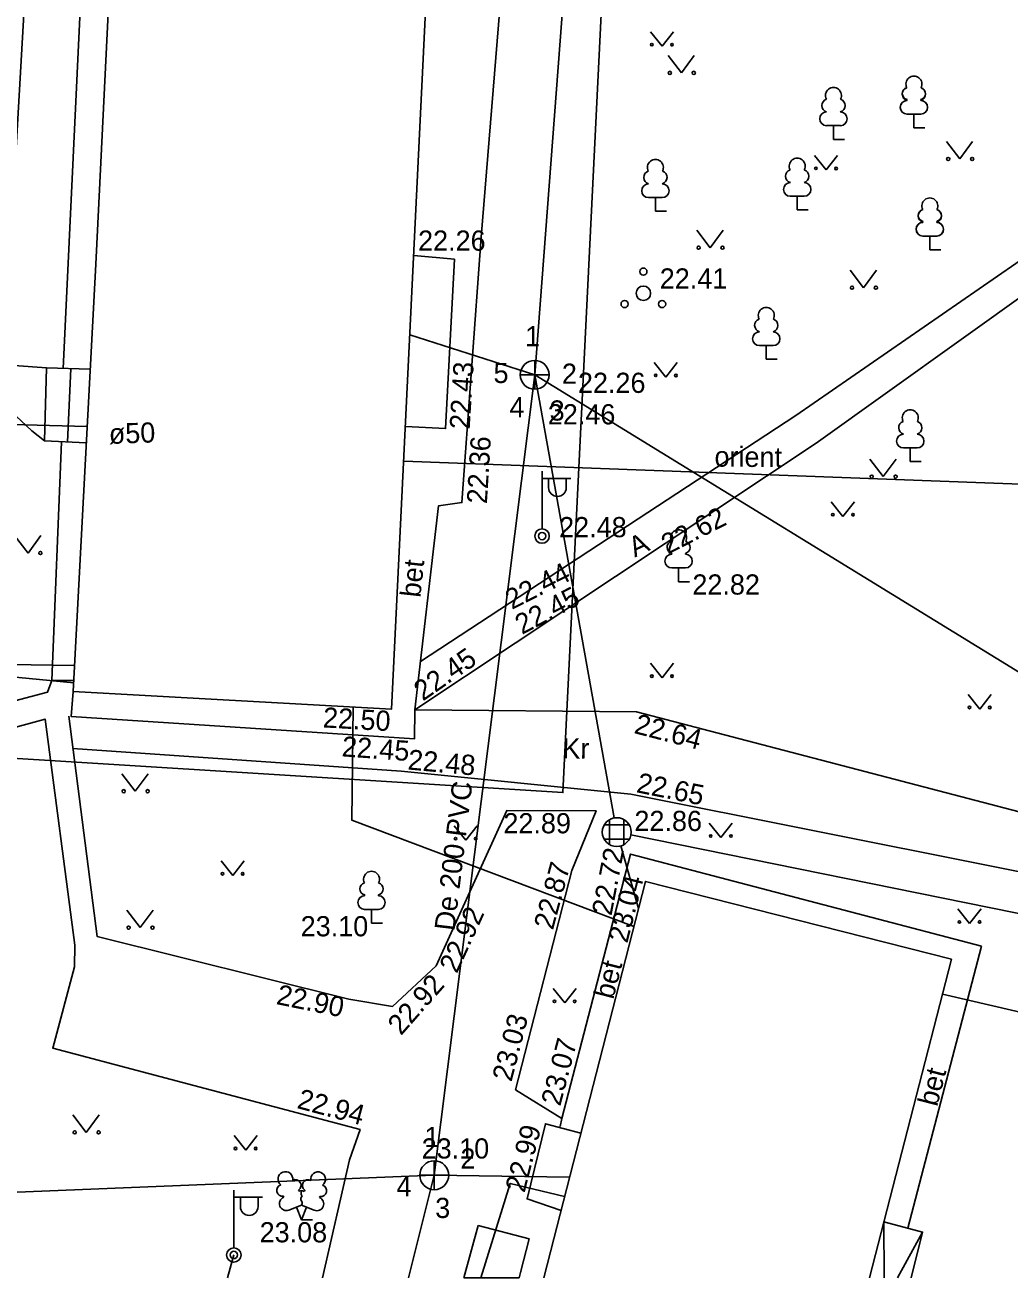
# Model space of a CAD drawing. Extents: x 714391 to 714584, y 6589993 to 6590151.
# Drawn here: x 714456.74 to 714490.89, y 6589992.71 to 6590036.16 of the extents above; entities that cross this region are included whole.
import ezdxf

# ---------------------------------------------------------------- set-up
doc = ezdxf.new("R2010")
doc.units = 0
for name, color, linetype in [('DKAEV', 7, 'Continuous'), ('HALJASTUS', 7, 'Continuous'), ('HOONE', 7, 'Continuous'), ('HOONEDET', 7, 'Continuous'), ('KKAEV', 7, 'Continuous'), ('KORGUS', 7, 'Continuous'), ('KTRASS', 7, 'Continuous'), ('MPKAABEL', 7, 'Continuous'), ('POST', 7, 'Continuous'), ('PUU', 7, 'Continuous'), ('SITRASS', 7, 'Continuous'), ('SKTRASS', 7, 'Continuous'), ('TEE', 7, 'Continuous'), ('TORU NR', 7, 'Continuous'), ('TTRASS', 7, 'Continuous'), ('Слой 1', 7, 'Continuous')]:
    doc.layers.add(name, color=color, linetype=linetype)

msp = doc.modelspace()

# ---------------------------------------------------------------- linework, layer by layer
at = {"layer": 'DKAEV'}
for p, q in [((714476.824, 6590008.422), (714477.69, 6590008.422)), ((714477.007, 6590007.739), (714477.007, 6590008.605)), ((714477.507, 6590008.605), (714477.507, 6590007.739)), ((714477.69, 6590007.922), (714476.824, 6590007.922))]:
    msp.add_line(p, q, dxfattribs=at)
msp.add_circle((714477.257, 6590008.172), 0.5, dxfattribs=at)
at = {"layer": 'HALJASTUS'}
for p, q in [((714478.422, 6590035.928), (714478.827, 6590035.423)), ((714478.827, 6590035.423), (714479.222, 6590035.928)), ((714479.037, 6590035.107), (714479.5, 6590034.5)), ((714479.5, 6590034.5), (714479.946, 6590035.107)), ((714488.691, 6590032.123), (714489.154, 6590031.516)), ((714489.154, 6590031.516), (714489.6, 6590032.123)), ((714484.111, 6590031.638), (714484.516, 6590031.133)), ((714484.516, 6590031.133), (714484.911, 6590031.638)), ((714480.034, 6590029.044), (714480.497, 6590028.437)), ((714480.497, 6590028.437), (714480.943, 6590029.044)), ((714485.354, 6590027.657), (714485.817, 6590027.05)), ((714485.817, 6590027.05), (714486.263, 6590027.657)), ((714478.558, 6590024.459), (714478.963, 6590023.954)), ((714478.963, 6590023.954), (714479.358, 6590024.459)), ((714486.037, 6590021.107), (714486.5, 6590020.5)), ((714486.5, 6590020.5), (714486.946, 6590021.107)), ((714484.698, 6590019.627), (714485.103, 6590019.122)), ((714485.103, 6590019.122), (714485.498, 6590019.627)), ((714456.377, 6590018.457), (714456.84, 6590017.85)), ((714456.84, 6590017.85), (714457.286, 6590018.457)), ((714478.422, 6590014.028), (714478.827, 6590013.523)), ((714478.827, 6590013.523), (714479.222, 6590014.028)), ((714489.439, 6590012.945), (714489.844, 6590012.44)), ((714489.844, 6590012.44), (714490.239, 6590012.945)), ((714460.097, 6590010.197), (714460.56, 6590009.59)), ((714460.56, 6590009.59), (714461.006, 6590010.197)), ((714471.615, 6590008.395), (714472.02, 6590007.89)), ((714472.02, 6590007.89), (714472.415, 6590008.395)), ((714480.465, 6590008.486), (714480.87, 6590007.981)), ((714480.87, 6590007.981), (714481.265, 6590008.486)), ((714463.533, 6590007.176), (714463.938, 6590006.671)), ((714463.938, 6590006.671), (714464.333, 6590007.176)), ((714460.267, 6590005.467), (714460.73, 6590004.86)), ((714460.73, 6590004.86), (714461.176, 6590005.467)), ((714489.09, 6590005.506), (714489.495, 6590005.001)), ((714489.495, 6590005.001), (714489.89, 6590005.506)), ((714475.047, 6590002.751), (714475.452, 6590002.246)), ((714475.452, 6590002.246), (714475.847, 6590002.751)), ((714458.397, 6589998.367), (714458.86, 6589997.76)), ((714458.86, 6589997.76), (714459.306, 6589998.367)), ((714463.984, 6589997.649), (714464.389, 6589997.144)), ((714464.389, 6589997.144), (714464.784, 6589997.649))]:
    msp.add_line(p, q, dxfattribs=at)
for centre, radius in [((714478.474, 6590035.478), 0.0428), ((714479.174, 6590035.478), 0.0452), ((714479.099, 6590034.5), 0.055), ((714479.928, 6590034.5), 0.055), ((714488.753, 6590031.516), 0.055), ((714489.582, 6590031.516), 0.055), ((714484.163, 6590031.188), 0.0428), ((714484.863, 6590031.188), 0.0452), ((714480.096, 6590028.437), 0.055), ((714480.925, 6590028.437), 0.055), ((714478.18, 6590027.609), 0.125), ((714478.18, 6590026.859), 0.25), ((714485.416, 6590027.05), 0.055), ((714486.245, 6590027.05), 0.055), ((714477.53, 6590026.484), 0.125), ((714478.83, 6590026.484), 0.125), ((714478.61, 6590024.009), 0.0428), ((714479.31, 6590024.009), 0.0452), ((714486.099, 6590020.5), 0.055), ((714486.928, 6590020.5), 0.055), ((714484.75, 6590019.178), 0.0428), ((714485.45, 6590019.178), 0.0452), ((714457.268, 6590017.85), 0.055), ((714478.474, 6590013.579), 0.0428), ((714479.174, 6590013.579), 0.0452), ((714489.491, 6590012.495), 0.0428), ((714490.191, 6590012.495), 0.0452), ((714460.159, 6590009.59), 0.055), ((714460.988, 6590009.59), 0.055), ((714471.667, 6590007.946), 0.0428), ((714472.367, 6590007.946), 0.0452), ((714480.517, 6590008.036), 0.0428), ((714481.217, 6590008.036), 0.0452), ((714463.585, 6590006.727), 0.0428), ((714464.285, 6590006.727), 0.0452), ((714460.329, 6590004.86), 0.055), ((714461.158, 6590004.86), 0.055), ((714489.142, 6590005.056), 0.0428), ((714489.842, 6590005.056), 0.0452), ((714475.099, 6590002.302), 0.0428), ((714475.799, 6590002.302), 0.0452), ((714458.459, 6589997.76), 0.055), ((714459.288, 6589997.76), 0.055), ((714464.036, 6589997.199), 0.0428), ((714464.736, 6589997.199), 0.0452)]:
    msp.add_circle(centre, radius, dxfattribs=at)
at = {"layer": 'HOONE'}
for points in [[(714458.41, 6590013.05), (714459.19, 6590027.87), (714460.78, 6590060.09), (714461.543, 6590073.769), (714472.409, 6590073.228), (714469.451, 6590012.441), (714458.41, 6590013.05)], [(714458.89, 6590022.24), (714455.84, 6590022.32), (714456.07, 6590025.65), (714456.9, 6590040.18), (714456.96, 6590042.47)], [(714470.216, 6590028.163), (714471.627, 6590028.037), (714471.323, 6590022.165), (714469.928, 6590022.237)], [(714474.728, 6589992.711), (714478.254, 6590006.46), (714488.871, 6590003.761)], [(714488.871, 6590003.761), (714486.02, 6589992.711)], [(714475.327, 6589995.047), (714474.146, 6589995.449), (714474.786, 6589998.057), (714476.016, 6589997.731)], [(714472.545, 6589992.711), (714473.561, 6589995.989), (714475.451, 6589995.53)], [(714487.462, 6589992.711), (714487.862, 6589994.302), (714486.522, 6589994.654)]]:
    msp.add_lwpolyline(points, dxfattribs=at)
at = {"layer": 'HOONEDET'}
for p, q in [((714486.522, 6589994.654), (714486.526, 6589992.711)), ((714487.862, 6589994.302), (714486.989, 6589992.711))]:
    msp.add_line(p, q, dxfattribs=at)
for points in [[(714458.41, 6590013.05), (714458.331, 6590012.184), (714470.239, 6590011.404), (714470.258, 6590012.413), (714471.076, 6590019.492), (714471.888, 6590019.599), (714472.556, 6590028.807), (714473.199, 6590036.732), (714473.546, 6590043.204), (714472.383, 6590044.92), (714472.511, 6590054.97), (714473.955, 6590057.113), (714474.332, 6590063.959), (714473.026, 6590065.846), (714473.46, 6590073.992), (714460.725, 6590074.548), (714460.31, 6590064.52)], [(714458.06, 6590024.25), (714458.89, 6590041.81)], [(714458.86, 6590021.67), (714457.41, 6590021.74), (714457.48, 6590024.27), (714459, 6590024.23)], [(714458.32, 6590024.25), (714458.21, 6590021.7)], [(714458.43, 6590013.43), (714457.67, 6590013.43), (714458, 6590021.71)]]:
    msp.add_lwpolyline(points, dxfattribs=at)
at = {"layer": 'KKAEV'}
for p, q in [((714474.411, 6590023.53), (714474.411, 6590024.53)), ((714473.911, 6590024.03), (714474.911, 6590024.03)), ((714470.929, 6589995.772), (714470.929, 6589996.772)), ((714470.429, 6589996.272), (714471.429, 6589996.272))]:
    msp.add_line(p, q, dxfattribs=at)
for centre in [(714474.411, 6590024.03), (714470.929, 6589996.272)]:
    msp.add_circle(centre, 0.5, dxfattribs=at)
at = {"layer": 'KTRASS'}
for p, q in [((714474.411, 6590024.03), (714475.65, 6590040.224)), ((714474.411, 6590024.03), (714470.082, 6590025.418)), ((714470.929, 6589996.272), (714474.411, 6590024.03)), ((714474.411, 6590024.03), (714496.65, 6590010.373)), ((714470.031, 6589992.711), (714470.929, 6589996.272)), ((714470.929, 6589996.272), (714475.624, 6589996.203))]:
    msp.add_line(p, q, dxfattribs=at)
msp.add_lwpolyline([(714438.332, 6589994.94), (714470.908, 6589996.272)], dxfattribs=at)
at = {"layer": 'MPKAABEL'}
for points in [[(714445.074, 6589992.711), (714446.96, 6590002.29), (714449.37, 6590014.23), (714458.43, 6590013.35)], [(714463.756, 6589992.711), (714463.977, 6589993.507)]]:
    msp.add_lwpolyline(points, dxfattribs=at)
at = {"layer": 'POST'}
for p, q in [((714474.668, 6590018.689), (714474.668, 6590020.689)), ((714474.668, 6590020.439), (714475.668, 6590020.439)), ((714474.895, 6590020.118), (714474.895, 6590020.439)), ((714475.507, 6590020.118), (714475.507, 6590020.439)), ((714474.668, 6590018.439), (714474.668, 6590018.439)), ((714463.977, 6589993.757), (714463.977, 6589995.757)), ((714463.977, 6589995.507), (714464.977, 6589995.507)), ((714464.204, 6589995.186), (714464.204, 6589995.507)), ((714464.816, 6589995.186), (714464.816, 6589995.507)), ((714463.977, 6589993.507), (714463.977, 6589993.507))]:
    msp.add_line(p, q, dxfattribs=at)
for centre, radius in [((714474.668, 6590018.439), 0.25), ((714474.668, 6590018.439), 0.127), ((714463.977, 6589993.507), 0.25), ((714463.977, 6589993.507), 0.127)]:
    msp.add_circle(centre, radius, dxfattribs=at)
for centre in [(714475.201, 6590020.118), (714464.51, 6589995.186)]:
    msp.add_arc(centre, 0.306, 180, 0, dxfattribs=at)
at = {"layer": 'PUU'}
for p, q in [((714487.323, 6590033.574), (714487.323, 6590033.544)), ((714487.803, 6590033.574), (714487.803, 6590033.544)), ((714487.803, 6590033.069), (714487.323, 6590033.069)), ((714487.803, 6590033.069), (714487.323, 6590033.069)), ((714487.563, 6590032.594), (714487.563, 6590033.069)), ((714487.563, 6590032.594), (714487.563, 6590033.069)), ((714485.013, 6590032.671), (714484.533, 6590032.671)), ((714484.773, 6590032.196), (714484.773, 6590032.671)), ((714487.943, 6590032.594), (714487.563, 6590032.594)), ((714487.943, 6590032.594), (714487.563, 6590032.594)), ((714485.153, 6590032.196), (714484.773, 6590032.196)), ((714478.837, 6590030.175), (714478.357, 6590030.175)), ((714478.597, 6590029.7), (714478.597, 6590030.175)), ((714483.756, 6590030.221), (714483.276, 6590030.221)), ((714483.516, 6590029.746), (714483.516, 6590030.221)), ((714478.977, 6590029.7), (714478.597, 6590029.7)), ((714483.896, 6590029.746), (714483.516, 6590029.746)), ((714487.875, 6590029.348), (714487.875, 6590029.318)), ((714488.355, 6590029.348), (714488.355, 6590029.318)), ((714488.355, 6590028.843), (714487.875, 6590028.843)), ((714488.355, 6590028.843), (714487.875, 6590028.843)), ((714488.115, 6590028.368), (714488.115, 6590028.843)), ((714488.115, 6590028.368), (714488.115, 6590028.843)), ((714488.495, 6590028.368), (714488.115, 6590028.368)), ((714488.495, 6590028.368), (714488.115, 6590028.368)), ((714482.683, 6590025.045), (714482.203, 6590025.045)), ((714482.443, 6590024.57), (714482.443, 6590025.045)), ((714482.823, 6590024.57), (714482.443, 6590024.57)), ((714487.677, 6590021.494), (714487.197, 6590021.494)), ((714487.437, 6590021.019), (714487.437, 6590021.494)), ((714487.817, 6590021.019), (714487.437, 6590021.019)), ((714479.162, 6590017.836), (714479.162, 6590017.806)), ((714479.642, 6590017.836), (714479.642, 6590017.806)), ((714479.642, 6590017.331), (714479.162, 6590017.331)), ((714479.402, 6590016.856), (714479.402, 6590017.331)), ((714479.782, 6590016.856), (714479.402, 6590016.856)), ((714468.513, 6590005.997), (714468.513, 6590005.967)), ((714468.993, 6590005.997), (714468.993, 6590005.967)), ((714468.993, 6590005.492), (714468.513, 6590005.492)), ((714468.753, 6590005.017), (714468.753, 6590005.492)), ((714469.133, 6590005.017), (714468.753, 6590005.017)), ((714465.708, 6589995.508), (714465.693, 6589995.548)), ((714466.238, 6589995.718), (714466.223, 6589995.753)), ((714466.423, 6589995.713), (714466.438, 6589995.753)), ((714466.948, 6589995.498), (714466.963, 6589995.538)), ((714465.883, 6589995.063), (714466.328, 6589995.238)), ((714466.323, 6589994.728), (714466.148, 6589995.168)), ((714466.323, 6589994.728), (714466.503, 6589995.168)), ((714466.328, 6589995.238), (714466.768, 6589995.058)), ((714466.703, 6589994.728), (714466.323, 6589994.728))]:
    msp.add_line(p, q, dxfattribs=at)
msp.add_lwpolyline([(714466.328, 6589995.733), (714466.308, 6589995.658), (714466.308, 6589995.638), (714466.318, 6589995.608), (714466.338, 6589995.573), (714466.343, 6589995.553), (714466.328, 6589995.518), (714466.303, 6589995.468), (714466.298, 6589995.443), (714466.303, 6589995.428), (714466.313, 6589995.398), (714466.348, 6589995.338), (714466.353, 6589995.318), (714466.348, 6589995.298), (714466.333, 6589995.263), (714466.328, 6589995.238)], dxfattribs=at)
for centre, radius, start, end in [((714487.563, 6590034.114), 0.277, 332.5799, 207.4201), ((714487.563, 6590034.114), 0.277, 332.5799, 207.4201), ((714484.603, 6590033.369), 0.233, 109.0217, 253.1415), ((714484.773, 6590033.716), 0.277, 332.5799, 207.4201), ((714484.943, 6590033.369), 0.233, 286.8508, 70.9859), ((714487.393, 6590033.767), 0.233, 109.0217, 253.1415), ((714487.373, 6590033.781), 0.212, 105.2441, 257.079), ((714487.753, 6590033.781), 0.212, 282.921, 74.7559), ((714487.733, 6590033.767), 0.233, 286.8508, 70.9859), ((714484.536, 6590032.908), 0.238, 90.0016, 269.3953), ((714485.01, 6590032.908), 0.238, 270.6047, 89.9984), ((714487.326, 6590033.306), 0.237, 90, 270), ((714487.326, 6590033.306), 0.238, 90.0016, 269.3953), ((714487.8, 6590033.306), 0.237, 270, 90), ((714487.8, 6590033.306), 0.238, 270.6047, 89.9984), ((714478.597, 6590031.22), 0.277, 332.5799, 207.4201), ((714483.516, 6590031.266), 0.277, 332.5799, 207.4201), ((714478.427, 6590030.873), 0.233, 109.0217, 253.1415), ((714478.767, 6590030.873), 0.233, 286.8508, 70.9859), ((714483.346, 6590030.919), 0.233, 109.0217, 253.1415), ((714483.686, 6590030.919), 0.233, 286.8508, 70.9859), ((714478.36, 6590030.412), 0.238, 90.0016, 269.3953), ((714478.834, 6590030.412), 0.238, 270.6047, 89.9984), ((714483.279, 6590030.458), 0.238, 90.0016, 269.3953), ((714483.753, 6590030.458), 0.238, 270.6047, 89.9984), ((714488.115, 6590029.888), 0.277, 332.5799, 207.4201), ((714488.115, 6590029.888), 0.277, 332.5799, 207.4201), ((714487.945, 6590029.541), 0.233, 109.0217, 253.1415), ((714487.925, 6590029.556), 0.212, 105.2441, 257.079), ((714488.305, 6590029.556), 0.212, 282.921, 74.7559), ((714488.285, 6590029.541), 0.233, 286.8508, 70.9859), ((714487.877, 6590029.08), 0.237, 90, 270), ((714487.877, 6590029.08), 0.238, 90.0016, 269.3953), ((714488.352, 6590029.08), 0.237, 270, 90), ((714488.352, 6590029.08), 0.238, 270.6047, 89.9984), ((714482.443, 6590026.09), 0.277, 332.5799, 207.4201), ((714482.273, 6590025.743), 0.233, 109.0217, 253.1415), ((714482.613, 6590025.743), 0.233, 286.8508, 70.9859), ((714482.206, 6590025.282), 0.238, 90.0016, 269.3953), ((714482.68, 6590025.282), 0.238, 270.6047, 89.9984), ((714487.437, 6590022.539), 0.277, 332.5799, 207.4201), ((714487.267, 6590022.192), 0.233, 109.0217, 253.1415), ((714487.607, 6590022.192), 0.233, 286.8508, 70.9859), ((714487.2, 6590021.731), 0.238, 90.0016, 269.3953), ((714487.674, 6590021.731), 0.238, 270.6047, 89.9984), ((714479.402, 6590018.376), 0.277, 332.5799, 207.4201), ((714479.212, 6590018.044), 0.212, 105.2441, 257.079), ((714479.592, 6590018.044), 0.212, 282.921, 74.7559), ((714479.164, 6590017.569), 0.237, 90, 270), ((714479.639, 6590017.569), 0.237, 270, 90), ((714468.753, 6590006.537), 0.277, 332.5799, 207.4201), ((714468.563, 6590006.205), 0.212, 105.2441, 257.079), ((714468.943, 6590006.205), 0.212, 282.921, 74.7559), ((714468.515, 6590005.73), 0.237, 90, 270), ((714468.99, 6590005.73), 0.237, 270, 90), ((714465.766, 6589996.142), 0.256, 111.5027, 232.5173), ((714465.766, 6589996.142), 0.256, 350.4856, 111.5002), ((714466.902, 6589996.133), 0.256, 67.6168, 188.6314), ((714466.902, 6589996.133), 0.256, 306.5997, 67.6143), ((714465.667, 6589995.746), 0.202, 106.2979, 277.8684), ((714466.109, 6589995.92), 0.202, 305.1345, 116.705), ((714466.556, 6589995.916), 0.202, 62.412, 233.9825), ((714466.995, 6589995.736), 0.202, 261.2486, 72.8191), ((714465.797, 6589995.286), 0.237, 111.5014, 291.5004), ((714466.327, 6589995.495), 0.237, 66.7655, 111.5015), ((714466.858, 6589995.278), 0.237, 247.6166, 67.6155)]:
    msp.add_arc(centre, radius, start, end, dxfattribs=at)
at = {"layer": 'SITRASS'}
msp.add_line((714469.869, 6590021.038), (714494.838, 6590020.104), dxfattribs=at)
at = {"layer": 'SKTRASS'}
for p, q in [((714477.164, 6590008.663), (714474.411, 6590024.03)), ((714477.747, 6590008.073), (714505.271, 6590002.487)), ((714477.394, 6590007.691), (714478.013, 6590005.52))]:
    msp.add_line(p, q, dxfattribs=at)
at = {"layer": 'TEE'}
for p, q in [((714487.35, 6589994.437), (714489.903, 6590004.218)), ((714471.959, 6589992.711), (714472.451, 6589994.53)), ((714472.451, 6589994.53), (714474.219, 6589994.069)), ((714474.219, 6589994.069), (714473.921, 6589992.902)), ((714473.921, 6589992.902), (714473.872, 6589992.711)), ((714473.872, 6589992.711), (714471.959, 6589992.711))]:
    msp.add_line(p, q, dxfattribs=at)
for points in [[(714470.452, 6590014.088), (714483.473, 6590022.62), (714491.732, 6590028.328), (714508.314, 6590039.422), (714510.811, 6590040.796), (714513.08, 6590041.27), (714515.342, 6590041.216), (714516.939, 6590047.426), (714520.722, 6590062.481)], [(714525.477, 6590005.373), (714525.684, 6590006.074), (714527.69, 6590005.573), (714531.538, 6590012.432), (714532.385, 6590015.369), (714531.445, 6590019.084), (714529.795, 6590023.709), (714527.067, 6590029.841), (714526.32, 6590032.242), (714526.158, 6590034.948), (714527.384, 6590039.748), (714530.089, 6590049.424), (714531.112, 6590053.289), (714520.888, 6590055.232), (714516.962, 6590040.074), (714512.15, 6590039.854), (714507.831, 6590037.94), (714505.233, 6590035.896), (714491.681, 6590027.029), (714484.169, 6590021.661), (714470.258, 6590012.413)], [(714458.41, 6590041.84), (714457.61, 6590042.45), (714451.01, 6590042.74), (714438.326, 6590043.121), (714437.835, 6590043.135), (714436.01, 6590043.19), (714428.72, 6590026.84), (714430.208, 6590026.691), (714430.977, 6590026.614), (714435.5, 6590026.16), (714448.72, 6590024.98), (714455.07, 6590024.44), (714457.48, 6590024.27)], [(714457.41, 6590021.74), (714456.97, 6590022.09), (714456.24, 6590022.77), (714455.28, 6590023.03), (714451.04, 6590023.38), (714437.45, 6590024.7), (714430.368, 6590025.27), (714429.927, 6590025.305), (714428, 6590025.46), (714417.4, 6590001.98), (714418.881, 6590001.433), (714419.464, 6590001.218), (714420.84, 6590000.71), (714421.59, 6590000.94), (714422.12, 6590001.13), (714422.82, 6590001)], [(714437.5, 6590007.72), (714457.52, 6590013.03), (714457.67, 6590013.43)], [(714470.258, 6590012.413), (714477.939, 6590012.342), (714506.57, 6590004.861), (714516.206, 6590003.294), (714514.878, 6590011.068), (714514.502, 6590013.311)], [(714437.21, 6590006.57), (714457.43, 6590012.09), (714458.46, 6590004.25), (714458.45, 6590003.5), (714457.7, 6590000.68), (714461.014, 6589999.801), (714462.195, 6589999.487), (714468.354, 6589997.853), (714467.989, 6589996.804), (714467.054, 6589992.711)], [(714458.256, 6590012.188), (714459.24, 6590004.55), (714459.24, 6590004.55), (714467.967, 6590002.381), (714469.48, 6590002.129), (714470.993, 6590003.538), (714473.446, 6590008.927), (714476.542, 6590008.914), (714475.705, 6590006.845), (714473.741, 6589999.238), (714475.357, 6589998.244)], [(714518.759, 6589992.711), (714516.445, 6590000.399), (714511.421, 6590002.696), (714502.998, 6590004.442), (714477.749, 6590009.482), (714469.779, 6590010.286), (714458.4, 6590011.077)], [(714475.299, 6589997.963), (714475.357, 6589998.244), (714477.73, 6590007.409), (714489.903, 6590004.218)]]:
    msp.add_lwpolyline(points, dxfattribs=at)
at = {"layer": 'TTRASS'}
for points in [[(714458.46, 6590013.95), (714450.12, 6590014.08), (714444.33, 6590004.71), (714436.07, 6590005.56)], [(714468.121, 6590012.519), (714468.07, 6590008.59), (714477.852, 6590004.894)], [(714509.087, 6590006.785), (714507.645, 6590001.299), (714506.85, 6589998.309), (714488.558, 6590002.554)]]:
    msp.add_lwpolyline(points, dxfattribs=at)
at = {"layer": 'Слой 1'}
msp.add_lwpolyline([(714455.78, 6590085.63), (714478.99, 6590085.97), (714478.28, 6590068.22), (714475.39, 6590009.54), (714423.1, 6590012.8)], close=True, dxfattribs=at)

# ---------------------------------------------------------------- texts
at = {"layer": 'HOONEDET'}
for rotation, p in [(83.7787, (714470.445, 6590016.287)), (75.6428, (714477.135, 6590002.346)), (75.6428, (714488.367, 6589998.627))]:
    msp.add_text('bet', height=0.7, rotation=rotation, dxfattribs=at).set_placement(p)
at = {"layer": 'KORGUS'}
for s, p in [('22.26', (714470.367, 6590028.335)), ('22.41', (714478.749, 6590027.021)), ('22.26', (714475.911, 6590023.403)), ('22.46', (714474.867, 6590022.312)), ('22.48', (714475.259, 6590018.398)), ('22.82', (714479.88, 6590016.409)), ('22.89', (714473.326, 6590008.13)), ('22.86', (714477.871, 6590008.21)), ('23.10', (714466.296, 6590004.558)), ('23.10', (714470.491, 6589996.852)), ('23.08', (714464.873, 6589993.945))]:
    msp.add_text(s, height=0.7, dxfattribs=at).set_placement(p)
for s, rotation, p in [('22.43', 86.5237, (714472.156, 6590022.122)), ('22.36', 86.5237, (714472.753, 6590019.542)), ('22.62', 26.9728, (714479.029, 6590017.792)), ('22.44', 26.7127, (714473.619, 6590015.875)), ('22.45', 27.8304, (714473.97, 6590015.008)), ('22.45', 34.804, (714470.534, 6590012.698)), ('22.50', 356.7805, (714467.054, 6590011.803)), ('22.64', 345.5044, (714477.826, 6590011.61)), ('22.45', 355.9858, (714467.706, 6590010.8)), ('22.48', 354.8461, (714469.991, 6590010.344)), ('22.65', 348.5955, (714477.91, 6590009.557)), ('22.72', 79.0923, (714477.073, 6590005.249)), ('22.87', 74.9425, (714475.043, 6590004.752)), ('23.04', 75.8304, (714477.623, 6590004.296)), ('22.92', 65.4418, (714471.711, 6590003.242)), ('22.92', 48.6522, (714469.776, 6590001.094)), ('22.90', 348.518, (714465.421, 6590002.212)), ('23.03', 75.551, (714473.605, 6589999.488)), ('23.07', 75.3643, (714475.297, 6589998.643)), ('22.94', 344.9407, (714466.137, 6589998.608)), ('22.99', 75.6082, (714474.058, 6589995.641))]:
    msp.add_text(s, height=0.7, rotation=rotation, dxfattribs=at).set_placement(p)
at = {"layer": 'KTRASS'}
msp.add_text('De 200 PVC ', height=0.7, rotation=83.047, dxfattribs=at).set_placement((714471.627, 6590004.726))
at = {"layer": 'SITRASS'}
msp.add_text('orient', height=0.7, rotation=359.4766, dxfattribs=at).set_placement((714480.644, 6590020.848))
at = {"layer": 'TEE'}
for s, rotation, p in [('A', 25.7141, (714477.884, 6590017.69)), ('Kr', 359.1491, (714475.367, 6590010.731))]:
    msp.add_text(s, height=0.7, rotation=rotation, dxfattribs=at).set_placement(p)
at = {"layer": 'TORU NR'}
for s, p in [('1', (714474.079, 6590025.02)), ('5', (714472.984, 6590023.745)), ('2', (714475.355, 6590023.719)), ('4', (714473.538, 6590022.559)), ('3', (714474.93, 6590022.443)), ('1', (714470.587, 6589997.251)), ('2', (714471.837, 6589996.503)), ('4', (714469.621, 6589995.537)), ('3', (714470.961, 6589994.79))]:
    msp.add_text(s, height=0.7, dxfattribs=at).set_placement(p)
msp.add_text('ø50', height=0.7, rotation=2.0348, dxfattribs=at).set_placement((714459.653, 6590021.631))

doc.saveas('drawing.dxf')
